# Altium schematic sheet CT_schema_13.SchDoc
size 254 x 194 mm
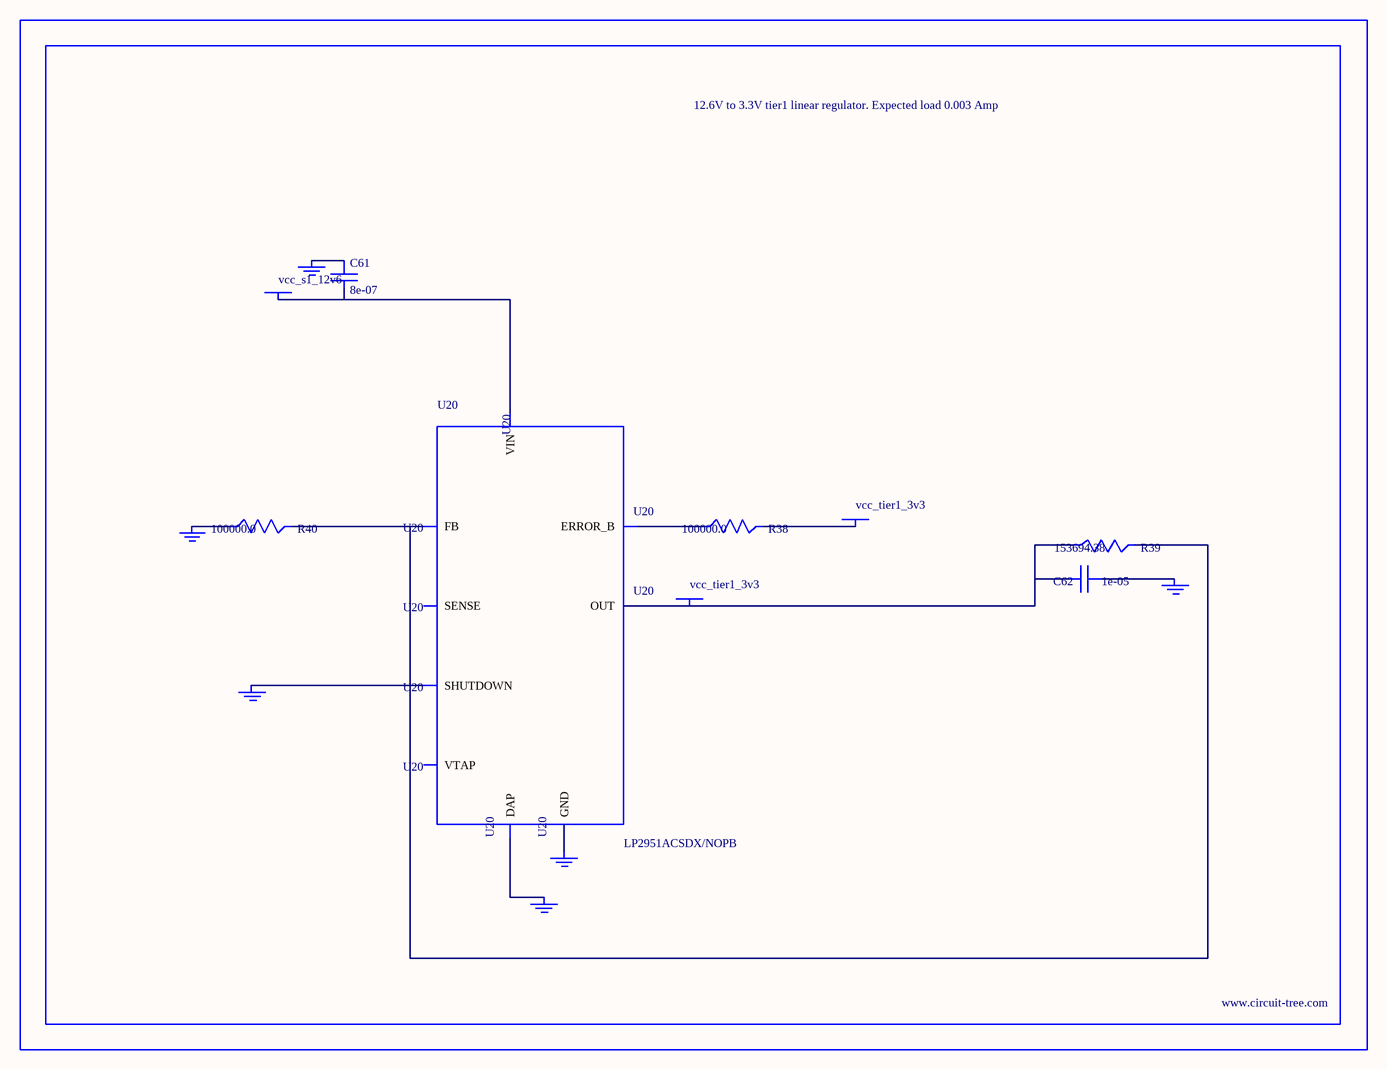
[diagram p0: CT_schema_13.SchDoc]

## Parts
BORDER12  (no value)
C61  8e-07  [R0603]
C62  1e-05  [C1210]
GND_INSTANCE_12_0  (no value)
GND_INSTANCE_12_1  (no value)
GND_INSTANCE_12_2  (no value)
GND_INSTANCE_12_3  (no value)
GND_INSTANCE_12_4  (no value)
GND_INSTANCE_12_5  (no value)
POWER_INSTANCE_12_0  vcc_tier1_3v3
POWER_INSTANCE_12_1  vcc_s1_12v6
POWER_INSTANCE_12_2  vcc_tier1_3v3
R38  100000.0  [R0603]
R39  153694.38  [R0603]
R40  100000.0  [R0603]
U20  LP2951ACSDX/NOPB  [WSON-8]

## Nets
NetC61_1: C61.1 GND_INSTANCE_12_3.0(GND)
NetC61_2: C61.2 POWER_INSTANCE_12_1.0(PWR) U20.8(VIN)
NetC62_1: C62.1 GND_INSTANCE_12_0.0(GND)
NetC62_2: C62.2 POWER_INSTANCE_12_2.0(PWR) R39.1 U20.1(OUT)
NetGND_INSTANCE_12_1_0: GND_INSTANCE_12_1.0(GND) U20.3(SHUTDOWN)
NetGND_INSTANCE_12_2_0: GND_INSTANCE_12_2.0(GND) R40.1
NetGND_INSTANCE_12_4_0: GND_INSTANCE_12_4.0(GND) U20.PAD(DAP)
NetGND_INSTANCE_12_5_0: GND_INSTANCE_12_5.0(GND) U20.4(GND)
NetPOWER_INSTANCE_12_0_0: POWER_INSTANCE_12_0.0(PWR) R38.2
NetR38_1: R38.1 U20.5(ERROR_B)
NetR39_2: R39.2 R40.2 U20.7(FB)

Not connected (* = marked no-connect by the designer): U20 2(SENSE) 6(VTAP)

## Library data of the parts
BORDER12 = BORDER_PAGE12
C61 = C61
C62 = GRM32DR61E106MA12L
GND_INSTANCE_12_0-GND_INSTANCE_12_5 = GND
POWER_INSTANCE_12_0-POWER_INSTANCE_12_2 = PWR
R38 R40 = RC0603JR-07100KL
R39 = R39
